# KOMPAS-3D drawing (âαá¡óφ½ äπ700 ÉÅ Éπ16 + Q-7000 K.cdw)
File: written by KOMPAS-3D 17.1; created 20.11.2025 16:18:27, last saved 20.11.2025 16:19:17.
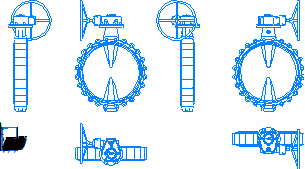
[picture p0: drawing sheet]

Sheet 1: A4, portrait

Title block, sheet 1: name: Сборка; material: Сталь 10  ГОСТ 1050-2013; mass: 489,63; sheets: 1; sheet format: A4

Views: Проекционный вид 5, Проекционный вид 6
Referenced files in \\adlc.lan\data\АДЛ_ПКД\3D-модели\ADL production\Дисковые поворотные затворы ГРАНВЭЛ\с резьбовыми проушинами с китайским редуктором Ру 16\KOMPAS 3D\: Гранвэл Ду700 РП Ру16 + Q-7000 K.m3d
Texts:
  Andrey
  АДЛ
Dimensions and other numbers on the sheet: 1:1; 1; 489,63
